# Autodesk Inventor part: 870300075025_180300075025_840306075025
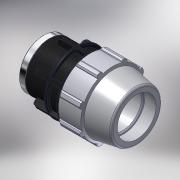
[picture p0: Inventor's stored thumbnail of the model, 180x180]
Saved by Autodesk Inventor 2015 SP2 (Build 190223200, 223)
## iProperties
Created: 2017-02
Part Number: 870300075025_180300075025_840306075025
Material: PVC-Piping
Description: PLASSON FEMALE ADAPTOR 75-2.1/2"
Document SubType Name: Modeling
Designer: KIM
Mass: 92.6774 g
Surface Area: 199.44 cm^2
Volume: 66.1981 cm^3
Density: 1.4 g/cm^3
Appearance: PTFE
Author: KIM
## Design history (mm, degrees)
derived "87030.ipt"
feature "Solid1::87030.ipt"
tag "TaggingFeature1"
body "Solid1"
other parameters: "d2" = 75, "d4" = 25, "d5" = 43.75, "d7" = 132, "d9" = 25, "d11" = 5, "d12" = 105.6, "d13" = 120 deg, "d14" = 97.5, "d15" = 10 deg, "d16" = 118.8, "d18" = 3.75, "d19" = 35 deg, "d20" = 17.5 deg, "d21" = 122.76, "d23" = 0, "d25" = 360 deg, "d27" = 2.64, "d34" = 6.6, "d35" = 52.5, "d36" = 0, "d42" = 43.75, "d43" = 3.96, "d46" = 2.25, "d49" = 137, "d51" = 175, "d53" = 1.5, "d55" = 360 deg, "d61" = 33, "d63" = 72.226, "d64" = 58.33333, "d65" = 6.6, "d69" = 95.04, "d70" = 3.3, "d71" = 12.6, "d72" = 0.5, "d73" = 1, "d_" = 75, "E_" = 132, "H_" = 175, "l_" = 137, "l_2" = 33, "Rp_Rc_" = 72.226
